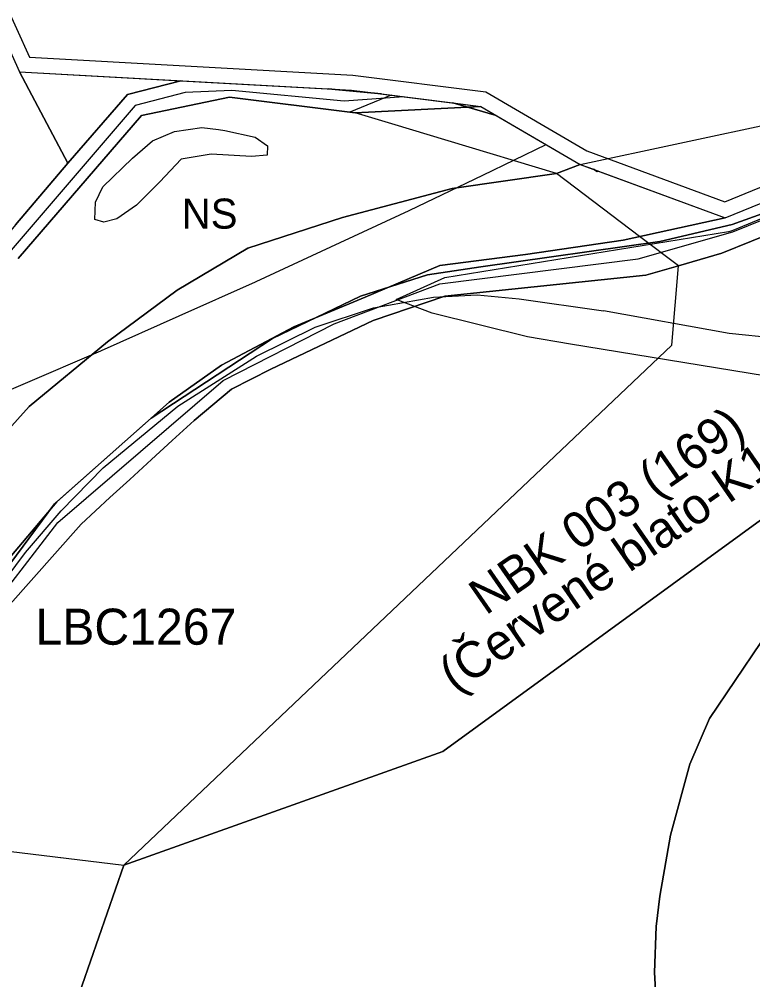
# Model space of a CAD drawing. Extents: x -758499 to -754160, y -1175205 to -1172032.
# Drawn here: x -756385.9 to -756141.7, y -1172898.6 to -1172578.8 of the extents above; entities that cross this region are included whole.
import ezdxf

# ---------------------------------------------------------------- set-up
doc = ezdxf.new("R2010")
doc.units = 0
for name, color, linetype in [('A041_BPEJ_p', 7, 'Continuous'), ('A044_VodZdr_op - 2a', 7, 'Continuous'), ('A053_ZvlPovoden_p', 7, 'Continuous'), ('A102_LetVysk_op', 7, 'Continuous'), ('D cyklocesty NÁVRH', 7, 'Continuous'), ('HRANICE katastrální', 7, 'Continuous'), ('HRANICE změn v krajině', 7, 'Continuous'), ('HRANICE řešeného území', 7, 'Continuous'), ('indexy RZV_TYP_1', 7, 'Continuous'), ('NÁVRH NZt zeměděl-trvalý travní porost', 7, 'Continuous'), ('PLOCHY NS smíšené nezastavěného území', 7, 'Continuous'), ('PLOCHY NZo zemědělské-orná půda', 7, 'Continuous'), ('PLOCHY PV prostranství veřejné', 7, 'Continuous'), ('PLOCHY VV vodní a vodohospodářské', 7, 'Continuous'), ('vrstevnice', 7, 'Continuous'), ('ÚSES LBC jako součást RBK', 7, 'Continuous'), ('ÚSES NBK funkční', 7, 'Continuous')]:
    doc.layers.add(name, color=color, linetype=linetype)

msp = doc.modelspace()

# ---------------------------------------------------------------- linework, layer by layer
at = {"layer": 'A041_BPEJ_p'}
for p, q in [((-756385.89, -1172596.03), (-756385.75, -1172596.35)), ((-756380.66, -1172606.04), (-756385.75, -1172596.35)), ((-756385.75, -1172596.35), (-756385.75, -1172596.35)), ((-756385.75, -1172596.35), (-756385.75, -1172596.35)), ((-756385.75, -1172596.35), (-756380.66, -1172606.04)), ((-756385.75, -1172596.35), (-756385.75, -1172596.35)), ((-756283.03, -1172602), (-756265.27, -1172603.69)), ((-756265.27, -1172603.69), (-756283.03, -1172602)), ((-756369.75, -1172626.8), (-756380.66, -1172606.04)), ((-756380.66, -1172606.04), (-756369.75, -1172626.8)), ((-756241.5, -1172606.69), (-756227.06, -1172610.87)), ((-756227.06, -1172610.87), (-756241.5, -1172606.69)), ((-756387.15, -1172647.25), (-756369.75, -1172626.8)), ((-756369.75, -1172626.8), (-756387.15, -1172647.25)), ((-756194.75, -1172628.8), (-756193.49, -1172629.53)), ((-756193.49, -1172629.53), (-756194.75, -1172628.8)), ((-756193.49, -1172629.53), (-756193.05, -1172629.43)), ((-756193.05, -1172629.43), (-756193.49, -1172629.53)), ((-756126.57, -1172639.28), (-756148.52, -1172647.14)), ((-756148.52, -1172647.14), (-756126.57, -1172639.28)), ((-756148.52, -1172647.14), (-756172.63, -1172652.83)), ((-756172.63, -1172652.83), (-756148.52, -1172647.14)), ((-756172.63, -1172652.83), (-756232.24, -1172661.23)), ((-756232.24, -1172661.23), (-756172.63, -1172652.83)), ((-756232.24, -1172661.23), (-756250, -1172663.94)), ((-756250, -1172663.94), (-756232.24, -1172661.23)), ((-756250, -1172663.94), (-756272.28, -1172671.03)), ((-756272.28, -1172671.03), (-756250, -1172663.94)), ((-756272.28, -1172671.03), (-756301.54, -1172685.12)), ((-756301.54, -1172685.12), (-756272.28, -1172671.03)), ((-756301.54, -1172685.12), (-756341.91, -1172711.67)), ((-756341.91, -1172711.67), (-756301.54, -1172685.12)), ((-756341.91, -1172711.67), (-756374.15, -1172740.12)), ((-756374.15, -1172740.12), (-756341.91, -1172711.67)), ((-756374.15, -1172740.12), (-756417.51, -1172798.64)), ((-756417.51, -1172798.64), (-756374.15, -1172740.12)), ((-756139.05, -1172786.3), (-756156.14, -1172811.59)), ((-756156.14, -1172811.59), (-756139.05, -1172786.3)), ((-756156.14, -1172811.59), (-756162.58, -1172826.79)), ((-756162.58, -1172826.79), (-756156.14, -1172811.59)), ((-756162.58, -1172826.79), (-756169.07, -1172850.46)), ((-756169.07, -1172850.46), (-756162.58, -1172826.79)), ((-756169.07, -1172850.46), (-756172.57, -1172870.76)), ((-756172.57, -1172870.76), (-756169.07, -1172850.46)), ((-756172.57, -1172870.76), (-756173.89, -1172880.91)), ((-756173.89, -1172880.91), (-756172.57, -1172870.76)), ((-756173.89, -1172880.91), (-756174.4, -1172896.15)), ((-756174.4, -1172896.15), (-756173.89, -1172880.91)), ((-756174.4, -1172896.15), (-756171.3, -1172952.05)), ((-756171.3, -1172952.05), (-756174.4, -1172896.15))]:
    msp.add_line(p, q, dxfattribs=at)
for points in [[(-756385.75, -1172596.35), (-756283.03, -1172602)], [(-756283.03, -1172602), (-756275.26, -1172602.43), (-756265.27, -1172603.69)], [(-756265.27, -1172603.69), (-756241.5, -1172606.69)], [(-756241.5, -1172606.69), (-756232.21, -1172607.86), (-756227.06, -1172610.87)], [(-756227.06, -1172610.87), (-756199.1, -1172627.19), (-756194.75, -1172628.8)], [(-756193.05, -1172629.43), (-756150.9, -1172645), (-756101, -1172624.6), (-756099.58, -1172626.27)], [(-756194.75, -1172628.8), (-756193.05, -1172629.43)]]:
    msp.add_lwpolyline(points, dxfattribs=at)
at = {"layer": 'A044_VodZdr_op - 2a'}
msp.add_lwpolyline([(-755980.78, -1172723.15), (-756202.39, -1172686.98), (-756216.66, -1172684.57), (-756248.37, -1172676.68), (-756260.38, -1172672.19), (-756244.18, -1172664.87), (-756149.78, -1172649.51), (-756149.57, -1172649.47), (-756148.2, -1172649.05), (-756098.77, -1172628.64)], dxfattribs=at)
at = {"layer": 'A053_ZvlPovoden_p'}
msp.add_lwpolyline([(-756445.9, -1172463.76), (-756391.34, -1172584.03), (-756385.75, -1172596.35), (-756275.26, -1172602.43), (-756232.21, -1172607.86), (-756199.1, -1172627.19), (-756150.9, -1172645), (-756101, -1172624.6), (-756098.34, -1172627.72), (-756093.7, -1172633.16), (-756091.39, -1172635.87), (-756079.85, -1172649.4), (-756066.6, -1172663.27), (-756047.4, -1172683.37), (-756037, -1172685.76), (-755989.02, -1172696.8), (-755987.22, -1172697.21), (-755981.08, -1172727.03), (-755906.48, -1172742.92)], dxfattribs=at)
at = {"layer": 'A102_LetVysk_op'}
for p, q in [((-756231.5, -1172630.72), (-756210.41, -1172620.59)), ((-756255.88, -1172642.44), (-756231.5, -1172630.72)), ((-756282.16, -1172654.62), (-756256.09, -1172642.54)), ((-756256.09, -1172642.54), (-756255.88, -1172642.44)), ((-756307.03, -1172666.15), (-756282.16, -1172654.62)), ((-756332.69, -1172677.61), (-756307.22, -1172666.24)), ((-756307.22, -1172666.24), (-756307.03, -1172666.15)), ((-756358.49, -1172689.13), (-756332.69, -1172677.61)), ((-756358.68, -1172689.21), (-756358.49, -1172689.13)), ((-756384.58, -1172700.34), (-756358.68, -1172689.21)), ((-756410.27, -1172711.38), (-756384.58, -1172700.34))]:
    msp.add_line(p, q, dxfattribs=at)
at = {"layer": 'D cyklocesty NÁVRH'}
for points in [[(-756257.81, -1172604.63), (-756277.68, -1172606.14), (-756315.08, -1172602.59), (-756330.66, -1172603.25), (-756347.33, -1172607.59), (-756388.57, -1172655.72), (-756418.43, -1172700.36), (-756431.91, -1172730.22), (-756445.78, -1172754.75), (-756465.5, -1172798.96), (-756480.72, -1172826), (-756491.88, -1172846.72), (-756516.01, -1172955.8), (-756520.65, -1172972.25), (-756530.43, -1173001.09), (-756535, -1173035.16), (-756529.71, -1173055.59), (-756511.74, -1173091.32), (-756494.49, -1173131.04), (-756482.46, -1173153.94), (-756461.29, -1173181.19), (-756433.17, -1173211.78), (-756414.04, -1173225.98)], [(-756214.08, -1173227), (-756241.33, -1173219.46), (-756286.85, -1173220.62), (-756322.8, -1173217.43), (-756354.39, -1173212.5), (-756381.79, -1173199.89), (-756417.74, -1173170.61), (-756435.71, -1173150.75), (-756457.6, -1173116.83), (-756469.77, -1173084.95), (-756473.4, -1173061.17), (-756473.4, -1173017.98), (-756464.7, -1172968.7), (-756449.34, -1172874.48), (-756444.12, -1172855.06), (-756432.52, -1172831.29), (-756399.47, -1172780.55), (-756373.09, -1172746.35), (-756318.01, -1172699.09), (-756281.05, -1172680.25), (-756245.83, -1172666.91), (-756179.88, -1172658.65), (-756148.28, -1172649.67), (-756097.31, -1172628.93)]]:
    msp.add_lwpolyline(points, dxfattribs=at)
at = {"layer": 'HRANICE katastrální'}
msp.add_lwpolyline([(-756199.1, -1172627.19), (-756132.75, -1172612.98), (-756088.06, -1172588.57)], dxfattribs=at)
at = {"layer": 'HRANICE změn v krajině'}
for points in [[(-756449.97, -1172919.32), (-756446.1, -1172879), (-756440.77, -1172860.21), (-756436.04, -1172850.16), (-756426.99, -1172830.93), (-756389.76, -1172774.55), (-756365.3, -1172746.95), (-756355.67, -1172738.1), (-756349.05, -1172732.02), (-756341.8, -1172725.36), (-756335.02, -1172719.13), (-756327.62, -1172712.45), (-756315.2, -1172701.98), (-756302.12, -1172695.28), (-756268.05, -1172679.11), (-756244.23, -1172671.05), (-756177.23, -1172664.02), (-756166.43, -1172660.91), (-756152, -1172656.76), (-756122.36, -1172644.69)], [(-756124.02, -1172734.64), (-756244.84, -1172822.66), (-756351.03, -1172860.42), (-756381.55, -1172948.3)]]:
    msp.add_lwpolyline(points, dxfattribs=at)
at = {"layer": 'HRANICE řešeného území'}
for points in [[(-756441.35, -1172461.69), (-756386.79, -1172581.96), (-756382.45, -1172591.52), (-756274.81, -1172597.45), (-756230.57, -1172603.03), (-756196.96, -1172622.65), (-756150.99, -1172639.64), (-756099.54, -1172618.6), (-756094.54, -1172624.48), (-756089.9, -1172629.92), (-756087.59, -1172632.63), (-756076.14, -1172646.05), (-756062.98, -1172659.82), (-756044.82, -1172678.83), (-756035.88, -1172680.89), (-755987.9, -1172691.93), (-755982.97, -1172693.05), (-755976.84, -1172722.82), (-755906.47, -1172737.81)], [(-756445.9, -1172463.76), (-756391.34, -1172584.03), (-756385.75, -1172596.35), (-756275.26, -1172602.43), (-756232.21, -1172607.86), (-756199.1, -1172627.19), (-756150.9, -1172645), (-756101, -1172624.6), (-756098.34, -1172627.72), (-756093.7, -1172633.16), (-756091.39, -1172635.87), (-756079.85, -1172649.4), (-756066.6, -1172663.27), (-756047.4, -1172683.37), (-756037, -1172685.76), (-755989.02, -1172696.8), (-755987.22, -1172697.21), (-755981.08, -1172727.03), (-755906.48, -1172742.92)]]:
    msp.add_lwpolyline(points, dxfattribs=at)
at = {"layer": 'NÁVRH NZt zeměděl-trvalý travní porost'}
for points in [[(-756449.97, -1172919.32), (-756446.1, -1172879), (-756440.77, -1172860.21), (-756436.04, -1172850.16), (-756426.99, -1172830.93), (-756389.76, -1172774.55), (-756365.3, -1172746.95), (-756355.67, -1172738.1), (-756349.05, -1172732.02), (-756341.8, -1172725.36), (-756335.02, -1172719.13), (-756327.62, -1172712.45), (-756315.2, -1172701.98), (-756302.12, -1172695.28), (-756268.05, -1172679.11), (-756244.23, -1172671.05), (-756177.23, -1172664.02), (-756166.43, -1172660.91), (-756152, -1172656.76), (-756122.36, -1172644.69)], [(-756124.02, -1172734.64), (-756244.84, -1172822.66), (-756351.03, -1172860.42), (-756381.55, -1172948.3)]]:
    msp.add_lwpolyline(points, dxfattribs=at)
at = {"layer": 'PLOCHY NS smíšené nezastavěného území'}
for p, q in [((-756334.25, -1172616.17), (-756325.09, -1172614.88)), ((-756325.09, -1172614.88), (-756319.54, -1172615.58)), ((-756319.54, -1172615.58), (-756317.39, -1172615.92)), ((-756341.47, -1172619.37), (-756334.25, -1172616.17)), ((-756317.39, -1172615.92), (-756307.31, -1172618.12)), ((-756307.31, -1172618.12), (-756303.29, -1172621)), ((-756348.17, -1172625.07), (-756341.47, -1172619.37)), ((-756303.29, -1172621), (-756303.38, -1172624.07)), ((-756358, -1172634.65), (-756348.17, -1172625.07)), ((-756322.02, -1172623.77), (-756331.94, -1172625.41)), ((-756308.58, -1172624.51), (-756322.02, -1172623.77)), ((-756303.38, -1172624.07), (-756308.58, -1172624.51)), ((-756331.94, -1172625.41), (-756339.07, -1172632.98)), ((-756360.54, -1172639.79), (-756358, -1172634.65)), ((-756339.07, -1172632.98), (-756346.88, -1172640.77)), ((-756360.71, -1172645.56), (-756360.54, -1172639.79)), ((-756346.88, -1172640.77), (-756353.36, -1172645.25)), ((-756357.73, -1172646.38), (-756360.71, -1172645.56)), ((-756353.36, -1172645.25), (-756357.73, -1172646.38))]:
    msp.add_line(p, q, dxfattribs=at)
msp.add_lwpolyline([(-756386.2, -1172658.47), (-756345.22, -1172610.85), (-756315.93, -1172604.77), (-756274.06, -1172609.98), (-756232.21, -1172607.86), (-756199.1, -1172627.19), (-756207.07, -1172630.18), (-756241.8, -1172635.19), (-756278.27, -1172644.87), (-756309.83, -1172655.02), (-756333.29, -1172669.04), (-756356.47, -1172686.22), (-756382.55, -1172707.72), (-756400.16, -1172727.17)], dxfattribs=at)
at = {"layer": 'PLOCHY NZo zemědělské-orná půda'}
for points in [[(-756445.9, -1172463.76), (-756391.34, -1172584.03), (-756385.75, -1172596.35), (-756332.06, -1172599.3), (-756349.8, -1172603.94), (-756369.75, -1172626.8), (-756387.15, -1172647.25), (-756392.62, -1172653.68), (-756423.58, -1172700.81), (-756428.14, -1172711.63), (-756435.23, -1172728.43), (-756438.4, -1172734.01), (-756448.89, -1172751.57), (-756469.11, -1172797.37), (-756478.77, -1172812.08), (-756495.4, -1172844.47), (-756500.62, -1172866.47), (-756506.59, -1172894.25), (-756519.89, -1172954.7)], [(-756085.79, -1173362.04), (-756109.32, -1173130.91), (-756149.72, -1173126.03), (-756289.68, -1173157.74), (-756316.23, -1173153.55), (-756339.42, -1173131.29), (-756354, -1173101.39), (-756373.65, -1173041.77), (-756381.55, -1172948.3), (-756351.03, -1172860.42), (-756244.84, -1172822.66), (-756124.02, -1172734.64), (-756010.77, -1172702.21), (-755999.27, -1172694.44), (-755989.02, -1172696.8), (-755987.22, -1172697.21), (-755981.08, -1172727.03), (-755906.48, -1172742.92)]]:
    msp.add_lwpolyline(points, dxfattribs=at)
at = {"layer": 'PLOCHY PV prostranství veřejné'}
for points in [[(-756387.15, -1172647.25), (-756369.75, -1172626.8), (-756349.8, -1172603.94), (-756332.06, -1172599.3), (-756275.26, -1172602.43), (-756232.21, -1172607.86), (-756274.06, -1172609.98), (-756315.93, -1172604.77), (-756345.22, -1172610.85), (-756386.2, -1172658.47)], [(-756467.3, -1172898.68), (-756456.01, -1172872.31), (-756446.9, -1172848.87), (-756434.91, -1172826.57), (-756419.22, -1172799.73), (-756390.21, -1172759.5), (-756373.33, -1172739.49), (-756335.92, -1172706.33), (-756318.59, -1172694.04), (-756294.46, -1172681.23), (-756270.76, -1172671.34), (-756245.83, -1172660.82), (-756217.3, -1172657.2), (-756184.87, -1172652.34), (-756150.9, -1172645), (-756101, -1172624.6)], [(-756122.36, -1172644.69), (-756152, -1172656.76), (-756166.43, -1172660.91), (-756177.23, -1172664.02), (-756244.23, -1172671.05), (-756268.05, -1172679.11), (-756302.12, -1172695.28), (-756315.2, -1172701.98), (-756327.62, -1172712.45), (-756335.02, -1172719.13), (-756341.8, -1172725.36), (-756349.05, -1172732.02), (-756355.67, -1172738.1), (-756365.3, -1172746.95), (-756389.76, -1172774.55), (-756426.99, -1172830.93), (-756436.04, -1172850.16), (-756440.77, -1172860.21), (-756446.1, -1172879), (-756449.97, -1172919.32)]]:
    msp.add_lwpolyline(points, dxfattribs=at)
at = {"layer": 'PLOCHY VV vodní a vodohospodářské'}
for p, q in [((-756334.25, -1172616.17), (-756325.09, -1172614.88)), ((-756325.09, -1172614.88), (-756319.54, -1172615.58)), ((-756319.54, -1172615.58), (-756317.39, -1172615.92)), ((-756341.47, -1172619.37), (-756334.25, -1172616.17)), ((-756317.39, -1172615.92), (-756307.31, -1172618.12)), ((-756307.31, -1172618.12), (-756303.29, -1172621)), ((-756348.17, -1172625.07), (-756341.47, -1172619.37)), ((-756303.29, -1172621), (-756303.38, -1172624.07)), ((-756358, -1172634.65), (-756348.17, -1172625.07)), ((-756322.02, -1172623.77), (-756331.94, -1172625.41)), ((-756308.58, -1172624.51), (-756322.02, -1172623.77)), ((-756303.38, -1172624.07), (-756308.58, -1172624.51)), ((-756331.94, -1172625.41), (-756339.07, -1172632.98)), ((-756360.54, -1172639.79), (-756358, -1172634.65)), ((-756339.07, -1172632.98), (-756346.88, -1172640.77)), ((-756360.71, -1172645.56), (-756360.54, -1172639.79)), ((-756346.88, -1172640.77), (-756353.36, -1172645.25)), ((-756357.73, -1172646.38), (-756360.71, -1172645.56)), ((-756353.36, -1172645.25), (-756357.73, -1172646.38))]:
    msp.add_line(p, q, dxfattribs=at)
msp.add_lwpolyline([(-756400.16, -1172727.17), (-756382.55, -1172707.72), (-756356.47, -1172686.22), (-756333.29, -1172669.04), (-756309.83, -1172655.02), (-756278.27, -1172644.87), (-756241.8, -1172635.19), (-756207.07, -1172630.18), (-756199.1, -1172627.19), (-756150.9, -1172645), (-756184.87, -1172652.34), (-756217.3, -1172657.2), (-756245.83, -1172660.82), (-756270.76, -1172671.34), (-756294.46, -1172681.23), (-756318.59, -1172694.04), (-756335.92, -1172706.33), (-756373.33, -1172739.49), (-756390.21, -1172759.5)], dxfattribs=at)
at = {"layer": 'vrstevnice'}
for p, q in [((-756267.98, -1172674.92), (-756247.95, -1172671.41)), ((-756267.98, -1172674.92), (-756247.95, -1172671.41)), ((-756247.95, -1172671.41), (-756233.42, -1172670.54)), ((-756247.95, -1172671.41), (-756233.42, -1172670.54)), ((-756233.42, -1172670.54), (-756219.42, -1172671.88)), ((-756233.42, -1172670.54), (-756219.42, -1172671.88)), ((-756219.42, -1172671.88), (-756191.38, -1172675.97)), ((-756219.42, -1172671.88), (-756191.38, -1172675.97)), ((-756287.32, -1172681.3), (-756267.98, -1172674.92)), ((-756287.32, -1172681.3), (-756267.98, -1172674.92)), ((-756149.49, -1172683.44), (-756191.38, -1172675.97)), ((-756149.49, -1172683.44), (-756191.38, -1172675.97)), ((-756306.92, -1172691.06), (-756287.32, -1172681.3)), ((-756306.92, -1172691.06), (-756287.32, -1172681.3)), ((-756119.98, -1172686.61), (-756149.49, -1172683.44)), ((-756119.98, -1172686.61), (-756149.49, -1172683.44)), ((-756333.08, -1172707.69), (-756306.92, -1172691.06)), ((-756333.08, -1172707.69), (-756306.92, -1172691.06)), ((-756357.92, -1172728.17), (-756333.08, -1172707.69)), ((-756357.92, -1172728.17), (-756333.08, -1172707.69)), ((-756371.95, -1172742.48), (-756357.92, -1172728.17)), ((-756371.95, -1172742.48), (-756357.92, -1172728.17)), ((-756383.78, -1172756.39), (-756371.95, -1172742.48)), ((-756383.78, -1172756.39), (-756371.95, -1172742.48)), ((-756399.67, -1172777.5), (-756383.78, -1172756.39)), ((-756399.67, -1172777.5), (-756383.78, -1172756.39))]:
    msp.add_line(p, q, dxfattribs=at)
at = {"layer": 'ÚSES LBC jako součást RBK'}
for p, q in [((-756315.93, -1172604.77), (-756345.22, -1172610.85)), ((-756275.88, -1172609.75), (-756315.93, -1172604.77)), ((-756345.22, -1172610.85), (-756386.2, -1172658.47)), ((-756274.06, -1172609.98), (-756275.88, -1172609.75)), ((-756261.87, -1172613.64), (-756274.06, -1172609.98)), ((-756243.09, -1172619.27), (-756261.87, -1172613.64)), ((-756207.07, -1172630.18), (-756243.09, -1172619.27)), ((-756179.34, -1172651.15), (-756207.07, -1172630.18)), ((-756166.43, -1172660.91), (-756179.34, -1172651.15)), ((-756168.58, -1172687.32), (-756166.43, -1172660.91)), ((-756246.54, -1172761.28), (-756168.58, -1172687.32)), ((-756351.03, -1172860.42), (-756246.54, -1172761.28)), ((-756406, -1172853.78), (-756351.03, -1172860.42))]:
    msp.add_line(p, q, dxfattribs=at)
at = {"layer": 'ÚSES NBK funkční'}
msp.add_line((-756262.09, -1172604.09), (-756275.88, -1172609.75), dxfattribs=at)
msp.add_lwpolyline([(-756354, -1173101.39), (-756374.5, -1173040.3), (-756382.1, -1172950.3), (-756351.03, -1172860.42), (-756244.84, -1172822.66), (-756124.02, -1172734.64), (-756010.77, -1172702.21), (-755999.27, -1172694.44)], dxfattribs=at)

# ---------------------------------------------------------------- texts
at = {"layer": 'indexy RZV_TYP_1'}
msp.add_text('NS', height=10, dxfattribs=at).set_placement((-756331.8, -1172648.55))
at = {"layer": 'ÚSES LBC jako součást RBK'}
msp.add_text('LBC1267', height=12, dxfattribs=at).set_placement((-756380.5, -1172787.06))
at = {"layer": 'ÚSES NBK funkční'}
for s, p in [('(Červené blato-K118)', (-756240.65, -1172803.35)), ('NBK 003 (169)', (-756230.6, -1172777.48))]:
    msp.add_text(s, height=12, rotation=34.7466, dxfattribs=at).set_placement(p)

doc.saveas('drawing.dxf')
